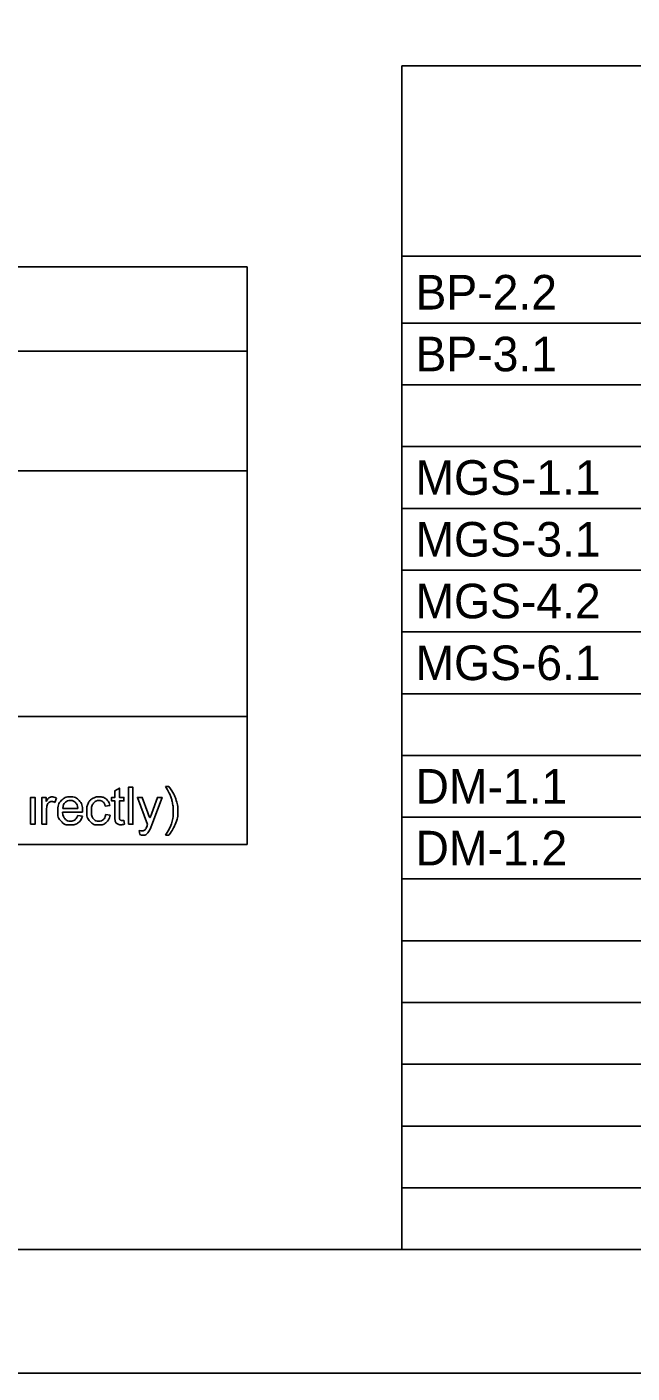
# Model space of a CAD drawing. Extents: x 0 to 34, y -1.2 to 22.
# Drawn here: x 9.73 to 12.18, y 0 to 5.45 of the extents above; entities that cross this region are included whole.
import ezdxf

# ---------------------------------------------------------------- set-up
doc = ezdxf.new("R2010")
doc.units = 0
for name, color, linetype in [('SH_Border', 7, 'Continuous'), ('SH_Cut_Line', 7, 'Continuous'), ('SH_Data', 7, 'Continuous')]:
    doc.layers.add(name, color=color, linetype=linetype)

msp = doc.modelspace()

# ---------------------------------------------------------------- linework, layer by layer
at = {"layer": 'SH_Border'}
msp.add_lwpolyline([(1.5, 21.5), (33.5, 21.5), (33.5, 0.5), (1.5, 0.5)], close=True, dxfattribs=at)
at = {"layer": 'SH_Cut_Line'}
msp.add_lwpolyline([(0, 0), (34, 0), (34, 22), (0, 22)], close=True, dxfattribs=at)
for points in [[(10.0892, 2.253), (10.0892, 2.3157), (10.0756, 2.3157), (10.0756, 2.33), (10.0892, 2.33), (10.0892, 2.3569), (10.1076, 2.368), (10.1076, 2.33), (10.126, 2.33), (10.126, 2.3157), (10.1076, 2.3157), (10.1076, 2.2519)], [(10.1437, 2.2212), (10.1437, 2.3713), (10.1621, 2.3713), (10.1621, 2.2212), (10.1437, 2.2212)], [(10.2945, 2.3738), (10.3077, 2.3738)], [(9.748, 2.2212), (9.748, 2.33), (9.7665, 2.33), (9.7665, 2.2212), (9.748, 2.2212)], [(9.7943, 2.2212), (9.7943, 2.33), (9.8109, 2.33), (9.8109, 2.3135)], [(9.8533, 2.3265), (9.8469, 2.3094)], [(10.0684, 2.2979), (10.0504, 2.2952)], [(10.2215, 2.2211), (10.1802, 2.33), (10.2, 2.33), (10.2227, 2.2672)], [(10.2382, 2.2665), (10.2614, 2.33), (10.2799, 2.33), (10.2386, 2.2193)], [(9.8127, 2.2781), (9.8127, 2.2212), (9.7943, 2.2212)], [(9.9583, 2.2708), (9.8771, 2.2708)], [(9.8781, 2.2859), (9.9389, 2.2859)], [(9.9387, 2.2563), (9.9578, 2.2539)], [(10.052, 2.261), (10.0701, 2.2586)], [(10.126, 2.2376), (10.1287, 2.2213)], [(10.1899, 2.1794), (10.1878, 2.1967)], [(10.3077, 2.177), (10.2945, 2.177)]]:
    msp.add_lwpolyline(points, dxfattribs=at)
for points in [[(10.2945, 2.177), (10.3251, 2.2261), (10.3251, 2.2754), (10.3251, 2.2947), (10.3207, 2.3136), (10.3172, 2.329), (10.3109, 2.3431), (10.307, 2.3523), (10.2945, 2.3738)], [(10.3077, 2.3738), (10.3269, 2.3481), (10.3362, 2.3222), (10.344, 2.2999), (10.344, 2.2755), (10.344, 2.2478), (10.3334, 2.222), (10.3228, 2.1962), (10.3077, 2.177)], [(9.8109, 2.3135), (9.8172, 2.325), (9.8226, 2.3287), (9.8279, 2.3324), (9.8344, 2.3324), (9.8437, 2.3324), (9.8533, 2.3265)], [(9.8469, 2.3094), (9.8401, 2.3134), (9.8334, 2.3134), (9.8274, 2.3134), (9.8226, 2.3098), (9.8178, 2.3061), (9.8158, 2.2997), (9.8127, 2.2898), (9.8127, 2.2781)], [(9.9578, 2.2539), (9.9533, 2.2372), (9.9411, 2.228), (9.9289, 2.2187), (9.9099, 2.2187), (9.8861, 2.2187), (9.8721, 2.2334), (9.8581, 2.2481), (9.8581, 2.2746), (9.8581, 2.3021), (9.8723, 2.3172), (9.8864, 2.3324), (9.9089, 2.3324), (9.9307, 2.3324), (9.9445, 2.3175), (9.9584, 2.3027), (9.9584, 2.2757), (9.9584, 2.2741), (9.9583, 2.2708)], [(9.9389, 2.2859), (9.9377, 2.2997), (9.9319, 2.3066), (9.9231, 2.3173), (9.9091, 2.3173), (9.8964, 2.3173), (9.8877, 2.3088), (9.8791, 2.3002), (9.8781, 2.2859)], [(10.0701, 2.2586), (10.0671, 2.2399), (10.0549, 2.2293), (10.0426, 2.2187), (10.0248, 2.2187), (10.0025, 2.2187), (9.9889, 2.2333), (9.9753, 2.2479), (9.9753, 2.2752), (9.9753, 2.2928), (9.9812, 2.306), (9.987, 2.3192), (9.9989, 2.3258), (10.0109, 2.3324), (10.0249, 2.3324), (10.0426, 2.3324), (10.0539, 2.3234), (10.0652, 2.3145), (10.0684, 2.2979)], [(10.0504, 2.2952), (10.0478, 2.3062), (10.0413, 2.3117), (10.0348, 2.3173), (10.0256, 2.3173), (10.0117, 2.3173), (10.003, 2.3073), (9.9943, 2.2973), (9.9943, 2.2757), (9.9943, 2.2537), (10.0027, 2.2438), (10.0111, 2.2339), (10.0246, 2.2339), (10.0355, 2.2339), (10.0428, 2.2405), (10.05, 2.2472), (10.052, 2.261)], [(9.8771, 2.2708), (9.8781, 2.2529), (9.8873, 2.2434), (9.8964, 2.2339), (9.91, 2.2339), (9.9202, 2.2339), (9.9273, 2.2392), (9.9345, 2.2446), (9.9387, 2.2563)], [(10.1287, 2.2213), (10.1209, 2.2197), (10.1148, 2.2197), (10.1047, 2.2197), (10.0992, 2.2228), (10.0937, 2.226), (10.0914, 2.2312), (10.0892, 2.2364), (10.0892, 2.253)], [(10.1076, 2.2519), (10.1076, 2.244), (10.1086, 2.2418), (10.1095, 2.2395), (10.1117, 2.2382), (10.1139, 2.2368), (10.118, 2.2368), (10.121, 2.2368), (10.126, 2.2376)], [(10.2227, 2.2672), (10.2271, 2.2552), (10.2306, 2.242), (10.2338, 2.2545), (10.2382, 2.2665)], [(10.1878, 2.1967), (10.1939, 2.1951), (10.1984, 2.1951), (10.2045, 2.1951), (10.2082, 2.1971), (10.2119, 2.1992), (10.2142, 2.2028), (10.216, 2.2056), (10.2198, 2.2166), (10.2204, 2.2181), (10.2215, 2.2211)], [(10.2386, 2.2193), (10.2319, 2.2014), (10.2282, 2.1947), (10.2233, 2.1856), (10.2169, 2.1813), (10.2106, 2.1771), (10.2018, 2.1771), (10.1965, 2.1771), (10.1899, 2.1794)]]:
    msp.add_open_spline(points, degree=3, dxfattribs=at)
at = {"layer": 'SH_Data'}
for p, q in [((11.25, 5.2917), (25.0339, 5.2917)), ((11.25, 0.5), (11.25, 5.2917)), ((11.25, 0.5), (11.25, 5.2917)), ((10.6247, 4.4775), (6.3747, 4.4775)), ((10.6247, 2.14), (10.6247, 4.4775)), ((11.25, 4.5209), (25.0339, 4.5209)), ((11.25, 4.25), (23.3089, 4.25)), ((6.3747, 4.136), (10.6247, 4.136)), ((11.25, 4), (23.3089, 4)), ((11.25, 3.75), (25.0339, 3.75)), ((6.3747, 3.6526), (10.6247, 3.6526)), ((11.25, 3.5), (25.0339, 3.5)), ((11.25, 3.25), (25.0339, 3.25)), ((11.25, 3), (25.0339, 3)), ((11.25, 2.75), (25.0339, 2.75)), ((10.6247, 2.6579), (6.3747, 2.6579)), ((11.25, 2.5), (25.0339, 2.5)), ((11.25, 2.25), (25.0339, 2.25)), ((10.6247, 2.14), (6.3747, 2.14)), ((11.25, 2), (25.0339, 2)), ((11.25, 1.75), (25.0339, 1.75)), ((11.25, 1.5), (25.0339, 1.5)), ((11.25, 1.25), (25.0339, 1.25)), ((11.25, 1), (25.0339, 1)), ((11.25, 0.75), (25.0339, 0.75))]:
    msp.add_line(p, q, dxfattribs=at)

# ---------------------------------------------------------------- texts
at = {"layer": 'SH_Cut_Line'}
for s, p in [('BP-2.2', (11.305, 4.305)), ('BP-3.1', (11.305, 4.055)), ('MGS-1.1', (11.305, 3.555)), ('MGS-3.1', (11.305, 3.305)), ('MGS-4.2', (11.305, 3.055)), ('MGS-6.1', (11.305, 2.805)), ('DM-1.1', (11.305, 2.305)), ('DM-1.2', (11.305, 2.055))]:
    msp.add_text(s, height=0.14, dxfattribs=at).set_placement(p)

doc.saveas('drawing.dxf')
